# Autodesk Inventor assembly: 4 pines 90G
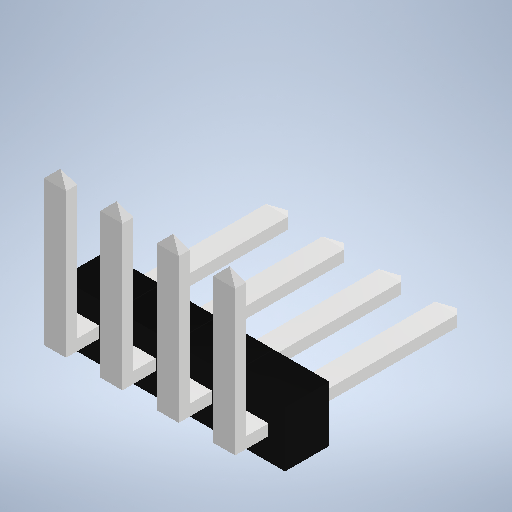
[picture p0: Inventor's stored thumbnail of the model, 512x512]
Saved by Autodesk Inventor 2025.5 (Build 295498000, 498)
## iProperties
Created: 2026-10
Part Number: 4 pines 90G
Description: FreeCAD Model
Document SubType Name: Assembly
Designer: Luis M
Authority: Unknown
Title: C:/Program Files (x86)/Labcenter Electronics/Proteus 8 Professional/DATA/MCAD/Espadines/Macho/90 Grados/4 pines 90G.step
Author: Author
Sending System: FreeCAD
Preprocessor: Open CASCADE STEP processor 6.8
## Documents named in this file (9)
- C:\Users\Luis M\Desktop\TESIS\CAD_TESIS\PCB\4 pines 90G.iam
- C:\Users\Luis M\Desktop\TESIS\CAD_TESIS\PCB\STEP\4 pines 90G\Pin_1.ipt
- C:\Users\Luis M\Desktop\TESIS\CAD_TESIS\PCB\STEP\4 pines 90G\Cuerpo_1.ipt
- C:\Users\Luis M\Desktop\TESIS\CAD_TESIS\PCB\STEP\4 pines 90G\Pin_3.ipt
- C:\Users\Luis M\Desktop\TESIS\CAD_TESIS\PCB\STEP\4 pines 90G\Cuerpo_3.ipt
- C:\Users\Luis M\Desktop\TESIS\CAD_TESIS\PCB\STEP\4 pines 90G\Pin_4.ipt
- C:\Users\Luis M\Desktop\TESIS\CAD_TESIS\PCB\STEP\4 pines 90G\Cuerpo_2.ipt
- C:\Users\Luis M\Desktop\TESIS\CAD_TESIS\PCB\STEP\4 pines 90G\Pin_2.ipt
- C:\Users\Luis M\Desktop\TESIS\CAD_TESIS\PCB\STEP\4 pines 90G\Cuerpo_4.ipt
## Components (8 placed, 8 different names)
1. 1
2. 2
3. 3
4. 4
5. 5
6. 6
7. 7
8. 8
